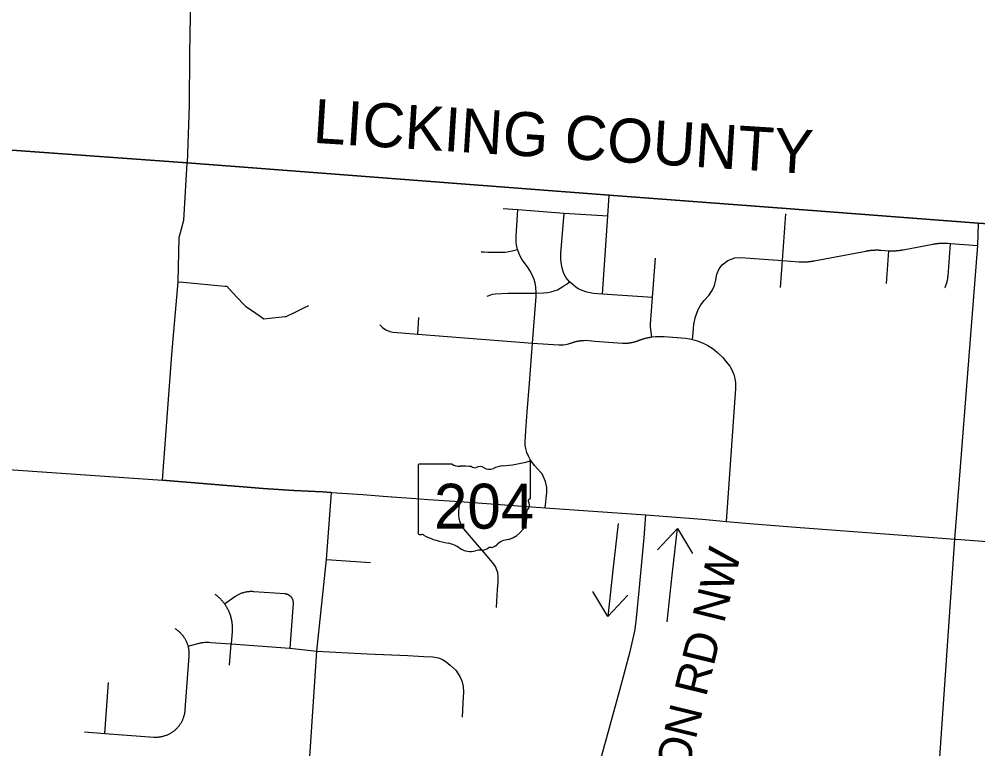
# Model space of a CAD drawing. Extents: x 1880545 to 1948545, y 79309 to 723051.
# Drawn here: x 1902373 to 1910544, y 700619 to 706837 of the extents above; entities that cross this region are included whole.
import ezdxf

# ---------------------------------------------------------------- set-up
doc = ezdxf.new("R2010")
doc.units = 0
for name, color, linetype in [('GM_X_County', 7, 'Continuous'), ('GM_X_County_Road', 7, 'Continuous'), ('GM_X_County_Text', 7, 'Continuous'), ('GM_X_State_Route', 7, 'Continuous'), ('GM_X_State_Shield', 7, 'Continuous'), ('GM_X_Township', 7, 'Continuous'), ('GM_X_Township_Road', 7, 'Continuous'), ('SH_Text', 7, 'Continuous')]:
    doc.layers.add(name, color=color, linetype=linetype)

msp = doc.modelspace()

# ---------------------------------------------------------------- linework, layer by layer
at = {"layer": 'GM_X_County'}
msp.add_lwpolyline([(1889271.5, 706620), (1891302.3, 706476.1), (1891973.7, 706452.7), (1893110.2, 706354.4), (1893306.8, 706337.4), (1894183.2, 706296.7), (1895332.2, 706215.1), (1898402.8, 705973), (1899946.7, 705888.4), (1900524.2, 705848.3), (1900987.7, 705813.2), (1901285.2, 705793.5), (1903803.3, 705612.3), (1907401, 705337.3), (1908909.6, 705222.3), (1910547.6, 705097.3), (1912287.5, 704989.5), (1913212.7, 704930.7), (1917682.9, 704647.7), (1918575.4, 704595.6), (1920101.7, 704497.5), (1921284.7, 704420.1), (1922414.3, 704343.6)], dxfattribs=at)
at = {"layer": 'GM_X_County_Road'}
for points in [[(1903834.8, 707192.1), (1903824.1, 706540.4), (1903822.2, 706103.6), (1903804.5, 705609.5)], [(1903743.6, 694852), (1904498.8, 695752), (1905984.5, 697482.2), (1906225.1, 697771.5), (1906330.5, 697904), (1906381.8, 698004.1), (1906482, 698229.9), (1906716.2, 698785.5), (1907022.1, 699505.3), (1907083, 699653.2), (1907147.2, 699860.4), (1907496.4, 701130), (1907579.5, 701447.1), (1907619.5, 701622.3), (1907630.8, 701703.2), (1907657.6, 701964), (1907699.4, 702415.6), (1907714.4, 702613)]]:
    msp.add_lwpolyline(points, dxfattribs=at)
at = {"layer": 'GM_X_State_Route'}
for p, q in [((1905552.5, 702766.9), (1905752.6, 702752.3)), ((1910015.3, 702431.2), (1910347, 702406.2)), ((1910347, 702406.2), (1910357.4, 702405.4)), ((1910357.4, 702405.4), (1910398.8, 702402.3))]:
    msp.add_line(p, q, dxfattribs=at)
for points in [[(1900688.5, 703112.5), (1900757.4, 703108), (1900954.3, 703093.6), (1901198.8, 703075.6), (1901679.7, 703043.6), (1902114.7, 703011.5), (1903595.5, 702908.8)], [(1903595.5, 702908.8), (1904451.7, 702836.1), (1904713.5, 702819.8), (1904959.1, 702807.4), (1905034.1, 702803)], [(1905034.1, 702803), (1905302.4, 702787.1), (1905547.2, 702767.3), (1905552.5, 702766.9)], [(1905752.6, 702752.3), (1905857.9, 702744.7), (1906127.5, 702727.2), (1906856.4, 702672.5), (1907714.4, 702613)], [(1907714.4, 702613), (1908192.9, 702574.4), (1908345.9, 702560.9)], [(1908345.9, 702560.9), (1908398.6, 702556.2), (1908634.1, 702537.2), (1908993.6, 702508), (1910015.3, 702431.2)], [(1910398.8, 702402.3), (1910957.8, 702359.4), (1912249.8, 702259.9), (1913033.6, 702197.6), (1913512.8, 702171.7), (1914434, 702136.7), (1915384.7, 702102.2), (1916119.3, 702053.7), (1916581.5, 702016.7), (1916959.5, 701996.7), (1917882.4, 701932.2)]]:
    msp.add_lwpolyline(points, dxfattribs=at)
at = {"layer": 'GM_X_State_Shield'}
for p, q in [((1906730.4, 702755.3), (1906730.4, 703059.3)), ((1905773.3, 703034.9), (1905773.3, 702453.8)), ((1906063, 703044.9), (1905782.7, 703044.9)), ((1906730.3, 702755.4), (1906730.4, 702755.3))]:
    msp.add_line(p, q, dxfattribs=at)
for centre, major_axis, start_param, end_param in [((1906389.5, 703837.2), (1015, 0), 4.814394, 5.042369), ((1906719.8, 703060.6), (10.7, 0), 6.141152, 7.989035), ((1905784.2, 703036.2), (11.1, 0), 1.712693, 3.28349), ((1906129.8, 703112.4), (107.5, 0), 4.042523, 4.731795), ((1906165.4, 702718.7), (386.1, 0), 1.404758, 1.657858), ((1906253.1, 703039.2), (31, 0), 3.836095, 5.185415), ((1906298.6, 702972), (64.5, 0), 0.950623, 2.079405), ((1906381.9, 703064.2), (77.6, 0), 4.081561, 5.145723), ((1906518.9, 702867.4), (204.2, 0), 1.699011, 2.107814), ((1906727.9, 702733), (16.5, 0), 1.883978, 3.671073), ((1906719, 702754.2), (11.4, 0), 5.05454, 6.418171), ((1906768.6, 702628.1), (72, 0), 2.387724, 3.262537), ((1906623, 702694.6), (99, 0), 5.934695, 6.695948), ((1906446.3, 702589.4), (253.9, 0), 5.101752, 6.440018), ((1905784.3, 702452.5), (11.2, 0), 3.00124, 4.508301), ((1905786, 702512), (85.4, 0), 4.665946, 4.897461), ((1905803.5, 702420.3), (30.8, 0), 0.519207, 1.627899), ((1906192.1, 702942.4), (733, 0), 4.195997, 4.488961), ((1905973.6, 702192.7), (229.3, 0), 0.823519, 1.323587), ((1906221.6, 702417.4), (145.5, 0), 4.026481, 4.996735), ((1906316.4, 702373.9), (77.5, 0), 4.691044, 5.507374), ((1906386.5, 702317.6), (21.8, 0), 1.147584, 2.315152), ((1906377.2, 702397.5), (82, 0), 4.937069, 5.64225), ((1906553.4, 702290.6), (139, 0), 1.647645, 2.488434), ((1906305.7, 702216.5), (119.6, 0), 1.495662, 1.94098)]:
    msp.add_ellipse(centre, major_axis=major_axis, ratio=0.8, start_param=start_param, end_param=end_param, dxfattribs=at)
at = {"layer": 'GM_X_Township'}
for points in [[(1922414.3, 704343.6), (1921284.7, 704420.1), (1920101.7, 704497.5), (1918575.4, 704595.6), (1917682.9, 704647.7), (1913212.7, 704930.7), (1912287.5, 704989.5), (1910547.6, 705097.3), (1908909.6, 705222.3), (1907401, 705337.3), (1903803.3, 705612.3), (1901285.2, 705793.5), (1900987.7, 705813.2), (1900524.2, 705848.3), (1899946.7, 705888.4), (1898402.8, 705973), (1895332.2, 706215.1), (1894183.2, 706296.7), (1893306.8, 706337.4), (1893110.2, 706354.4), (1891973.7, 706452.7), (1891302.3, 706476.1), (1889271.5, 706620), (1889456, 709272.2)], [(1901285.2, 705793.5), (1903803.3, 705612.3), (1907401, 705337.3), (1908909.6, 705222.3), (1910547.6, 705097.3), (1912287.5, 704989.5), (1913212.7, 704930.7), (1913032.4, 702200.4), (1912536.5, 694688.9), (1912502.9, 694180), (1912347.1, 691452.4), (1912324.5, 691136.3)]]:
    msp.add_lwpolyline(points, dxfattribs=at)
at = {"layer": 'GM_X_Township_Road'}
for p, q in [((1909765.6, 704584.5), (1909786.3, 704863.7)), ((1910310.1, 704925.6), (1910543.7, 704908.7)), ((1905771.2, 704152.8), (1905779.1, 704293.3)), ((1904991.6, 702232.3), (1905368.2, 702205.6)), ((1904166.7, 701332.6), (1904180, 701512.1)), ((1903103.2, 700750), (1903135.1, 701183.8))]:
    msp.add_line(p, q, dxfattribs=at)
for points in [[(1903595.5, 702908.8), (1903673.8, 703980.5), (1903727.5, 704598.7), (1903736.8, 704975.6), (1903776.4, 705124), (1903804.5, 705609.5)], [(1907344.1, 704494.7), (1907390, 705159.9), (1907402.2, 705334.5)], [(1906499.1, 705223.2), (1906623.5, 705213.6), (1907016.6, 705183.2), (1907390, 705159.9)], [(1906748.6, 704076.5), (1906778.6, 704473.7), (1906778.3, 704503), (1906775.9, 704555.1), (1906770.3, 704586.9), (1906761.8, 704618.3), (1906743.6, 704663.3), (1906726.4, 704695), (1906705.6, 704725.4), (1906676.6, 704764), (1906657.6, 704792.4), (1906640.3, 704822.4), (1906630.2, 704846.3), (1906619.8, 704873.7), (1906615.9, 704899), (1906613, 704913.4), (1906610.2, 704931.1), (1906609.7, 704953.6), (1906610.2, 704983.6), (1906613, 705031), (1906623.5, 705213.6)], [(1907770.7, 704465.4), (1907344.1, 704494.7), (1907269.3, 704499.9), (1907238.6, 704503.6), (1907210.3, 704509.9), (1907170.7, 704523.9), (1907138.6, 704539.5), (1907116.8, 704554.3), (1907094, 704572.1), (1907063.3, 704597.4), (1907035.9, 704632.4), (1907016.4, 704668.8), (1907000.5, 704714.8), (1906991.2, 704762.4), (1906989.2, 704794.8), (1906990.9, 704843.4), (1906995.9, 704908.3), (1907016.6, 705183.2)], [(1908861, 704551.2), (1908878.1, 704780.6), (1908907.6, 705177)], [(1910347, 702406.2), (1910543.7, 704908.7), (1910548.7, 705094.5)], [(1906311.3, 704854), (1906335.6, 704853.3), (1906366.9, 704851.7), (1906408.8, 704851.5), (1906454.8, 704850.6), (1906491.7, 704850.7), (1906515.2, 704851.9), (1906532.3, 704854.4), (1906574.7, 704862.6), (1906619.8, 704873.7)], [(1908878.1, 704780.6), (1909020.2, 704770), (1909024.2, 704769.7), (1909028.2, 704769.5), (1909032.1, 704769.3), (1909036.1, 704769.1), (1909040.1, 704768.9), (1909044.1, 704768.8), (1909048.2, 704768.7), (1909052.2, 704768.7), (1909056.2, 704768.6), (1909060.1, 704768.6), (1909064.1, 704768.7), (1909068.1, 704768.7), (1909072.1, 704768.9), (1909076.1, 704769), (1909080.1, 704769.2), (1909084.1, 704769.4), (1909088.1, 704769.6), (1909092.1, 704769.9), (1909096.1, 704770.1), (1909100.1, 704770.5), (1909104.1, 704770.8), (1909108.1, 704771.2), (1909112, 704771.7), (1909116, 704772.1), (1909120, 704772.6), (1909123.9, 704773.1), (1909127.9, 704773.7), (1909131.9, 704774.2), (1909135.8, 704774.8), (1909139.8, 704775.5), (1909143.7, 704776.2), (1909147.6, 704776.9), (1909589.9, 704861.1), (1909593.9, 704861.8), (1909597.8, 704862.5), (1909601.8, 704863.2), (1909605.7, 704863.8), (1909609.7, 704864.4), (1909613.6, 704865), (1909617.6, 704865.5), (1909621.5, 704866), (1909625.5, 704866.5), (1909629.5, 704867), (1909633.5, 704867.4), (1909637.5, 704867.8), (1909641.4, 704868.1), (1909645.4, 704868.4), (1909649.4, 704868.7), (1909653.4, 704869), (1909657.4, 704869.2), (1909661.4, 704869.4), (1909665.4, 704869.6), (1909669.4, 704869.7), (1909673.4, 704869.8), (1909677.4, 704869.8), (1909681.4, 704869.9), (1909685.4, 704869.9), (1909689.4, 704869.8), (1909693.4, 704869.8), (1909697.4, 704869.7), (1909701.4, 704869.6), (1909705.4, 704869.4), (1909709.4, 704869.2), (1909713.4, 704869), (1909717.4, 704868.7), (1909786.3, 704863.7)], [(1909786.3, 704863.7), (1909790.3, 704863.5), (1909794.3, 704863.3), (1909798.3, 704863.2), (1909802.3, 704863), (1909806.3, 704863), (1909810.3, 704862.9), (1909814.3, 704862.9), (1909818.3, 704862.9), (1909822.3, 704863), (1909826.3, 704863), (1909830.3, 704863.2), (1909834.3, 704863.3), (1909838.3, 704863.5), (1909842.3, 704863.7), (1909846.3, 704863.9), (1909850.3, 704864.2), (1909854.3, 704864.5), (1909858.3, 704864.8), (1909862.2, 704865.2), (1909866.2, 704865.6), (1909870.2, 704866), (1909874.2, 704866.5), (1909878.1, 704867), (1909882.1, 704867.5), (1909886.1, 704868), (1909890, 704868.6), (1909894, 704869.3), (1909897.9, 704869.9), (1909901.9, 704870.6), (1909907.7, 704871.7), (1910159.9, 704919.6), (1910163.9, 704920.3), (1910167.8, 704921), (1910171.7, 704921.7), (1910175.7, 704922.3), (1910179.6, 704922.9), (1910183.6, 704923.5), (1910187.6, 704924), (1910191.5, 704924.5), (1910195.5, 704925), (1910199.5, 704925.5), (1910203.5, 704925.9), (1910207.4, 704926.2), (1910211.4, 704926.6), (1910215.4, 704926.9), (1910219.4, 704927.2), (1910223.4, 704927.5), (1910227.4, 704927.7), (1910231.4, 704927.9), (1910235.4, 704928.1), (1910239.4, 704928.2), (1910243.4, 704928.2), (1910247.4, 704928.3), (1910251.4, 704928.3), (1910255.4, 704928.3), (1910259.4, 704928.3), (1910263.4, 704928.2), (1910267.4, 704928.2), (1910271.4, 704928), (1910275.4, 704927.9), (1910279.4, 704927.7), (1910283.4, 704927.5), (1910289.2, 704927.1), (1910310.1, 704925.6)], [(1910262.8, 704547.4), (1910264.3, 704550.6), (1910266, 704554.2), (1910267.6, 704557.8), (1910269.2, 704561.5), (1910270.7, 704565.2), (1910272.2, 704568.9), (1910273.6, 704572.7), (1910275, 704576.4), (1910276.3, 704580.2), (1910277.5, 704584), (1910278.8, 704587.8), (1910279.9, 704591.7), (1910281, 704595.5), (1910282, 704599.4), (1910283, 704603.2), (1910283.9, 704607.2), (1910284.8, 704611.1), (1910285.6, 704615), (1910286.3, 704618.9), (1910287, 704622.8), (1910287.6, 704626.8), (1910288.2, 704630.7), (1910288.7, 704634.7), (1910289.2, 704638.7), (1910289.6, 704642.7), (1910289.9, 704646.7), (1910310.1, 704925.6)], [(1907764.8, 704128.3), (1907753.7, 704212.2), (1907752.9, 704236.2), (1907770.7, 704465.4), (1907797.7, 704799.3)], [(1908111.9, 704106.7), (1908116.4, 704162.2), (1908119.8, 704204.8), (1908123.2, 704238.9), (1908136.1, 704299.3), (1908161.4, 704363.5), (1908183.3, 704402.1), (1908210.4, 704439.3), (1908250.6, 704482.9), (1908280.5, 704525.3), (1908299.6, 704568.2), (1908310.3, 704614.4), (1908319, 704663), (1908339.2, 704708.7), (1908365.4, 704743.2), (1908413.9, 704780.7), (1908471.9, 704801.9), (1908522.7, 704805.3), (1908600, 704799.5), (1908878.1, 704780.6)], [(1903727.5, 704598.7), (1903771.7, 704594.7), (1904125.4, 704562.3), (1904141.6, 704560.9), (1904191.3, 704508), (1904282.7, 704411.1), (1904305, 704387.4), (1904351.7, 704356), (1904425.4, 704306.5), (1904458.7, 704284.2), (1904507.2, 704289), (1904639.7, 704302.3), (1904649.3, 704303.3), (1904720.4, 704338), (1904800.2, 704377), (1904840.3, 704396.6)], [(1906778.3, 704503), (1906841.5, 704505.3), (1906874.6, 704507.8), (1906907.2, 704513.7), (1906940.1, 704523.3), (1906961.5, 704531.5), (1906984.3, 704544), (1907006, 704557.5), (1907024.1, 704569.8), (1907042.3, 704582.6), (1907063.3, 704597.4)], [(1906361.9, 704477.5), (1906392.9, 704487.7), (1906408.5, 704492.4), (1906432.6, 704496.6), (1906538.2, 704502.9), (1906778.3, 704503)], [(1905445.7, 704232.8), (1905468.1, 704209.3), (1905497.3, 704190.5), (1905532.9, 704175.8), (1905559, 704169), (1905771.2, 704152.8), (1906748.6, 704076.5), (1906973.8, 704060.4), (1906978.6, 704060.2), (1907011.2, 704061.3), (1907043.7, 704065.8), (1907074.6, 704076.2), (1907077.8, 704077.3), (1907081.6, 704078.6), (1907085.4, 704079.9), (1907090.7, 704081.7), (1907094.5, 704083), (1907098.3, 704084.3), (1907102.1, 704085.5), (1907106, 704086.6), (1907109.8, 704087.7), (1907113.7, 704088.7), (1907117.5, 704089.8), (1907121.4, 704090.7), (1907125.3, 704091.6), (1907129.3, 704092.4), (1907133.2, 704093.2), (1907137.1, 704093.9), (1907141, 704094.6), (1907145, 704095.2), (1907148.9, 704095.8), (1907152.9, 704096.4), (1907156.9, 704096.8), (1907160.9, 704097.2), (1907164.9, 704097.6), (1907168.8, 704097.9), (1907172.8, 704098.2), (1907176.8, 704098.4), (1907180.8, 704098.5), (1907184.8, 704098.6), (1907188.8, 704098.7), (1907198.6, 704100.8), (1907278.1, 704093.3), (1907476.5, 704079.7), (1907517.8, 704076.8), (1907522.5, 704076.6), (1907526.5, 704076.4), (1907530.5, 704076.2), (1907534.5, 704076.2), (1907538.5, 704076.2), (1907542.5, 704076.2), (1907546.5, 704076.2), (1907550.5, 704076.4), (1907554.5, 704076.6), (1907558.5, 704076.8), (1907562.5, 704077.1), (1907566.5, 704077.5), (1907570.4, 704077.9), (1907574.4, 704078.3), (1907578.4, 704078.8), (1907582.3, 704079.4), (1907586.3, 704080), (1907590.2, 704080.6), (1907594.2, 704081.4), (1907598.1, 704082.1), (1907602, 704082.9), (1907605.9, 704083.8), (1907609.8, 704084.7), (1907613.7, 704085.7), (1907617.5, 704086.7), (1907621.4, 704087.8), (1907625.2, 704089), (1907629.1, 704090.2), (1907632.9, 704091.4), (1907636.6, 704092.7), (1907640.4, 704094), (1907644.2, 704095.4), (1907647.9, 704096.8), (1907652.9, 704098.8), (1907656.6, 704100.2), (1907660.4, 704101.7), (1907664.1, 704103.1), (1907667.9, 704104.4), (1907671.7, 704105.7), (1907675.4, 704107), (1907679.3, 704108.3), (1907683.1, 704109.5), (1907686.9, 704110.7), (1907690.7, 704111.9), (1907694.5, 704113), (1907698.4, 704114.1), (1907702.2, 704115.2), (1907706.1, 704116.3), (1907709.9, 704117.3), (1907713.8, 704118.3), (1907717.7, 704119.2), (1907721.6, 704120.1), (1907725.5, 704121.1), (1907729.4, 704121.9), (1907733.3, 704122.7), (1907737.2, 704123.6), (1907741.2, 704124.3), (1907745.1, 704125.1), (1907749, 704125.8), (1907753, 704126.4), (1907756.9, 704127.1), (1907760.9, 704127.7), (1907764.8, 704128.3), (1907795.7, 704131.7), (1907834.6, 704133.3), (1907869.6, 704132.1), (1907943.6, 704126.2), (1908052.8, 704117), (1908089.4, 704111.5), (1908111.9, 704106.7), (1908152.5, 704095.2), (1908201.8, 704076.1), (1908242.8, 704055.2), (1908286.6, 704027.3), (1908325.8, 703996.3), (1908369.1, 703953.3), (1908400.2, 703917.1), (1908430, 703878.4), (1908447.4, 703848.1), (1908464.1, 703807.5), (1908472.9, 703774.6), (1908478.1, 703738), (1908478, 703688.9), (1908398.6, 702556.2)], [(1906819.9, 702972.4), (1906792.9, 703003.1), (1906768.4, 703030.9), (1906747.1, 703056.6), (1906728.4, 703084.3), (1906712.9, 703113.9), (1906700.4, 703144.8), (1906690.8, 703176.8), (1906685.9, 703206.4), (1906685.2, 703234.3), (1906687, 703277.2), (1906690.4, 703332.4), (1906702.1, 703489.9), (1906722.6, 703735.8), (1906748.6, 704076.5)], [(1905034.1, 702803), (1904959.1, 702807.4), (1904713.5, 702819.8), (1904451.7, 702836.1), (1903595.5, 702908.8)], [(1906856.4, 702672.5), (1906870.3, 702804.2), (1906871.1, 702846.3), (1906860, 702898), (1906830, 702960.9), (1906819.9, 702972.4)], [(1904498.8, 695752), (1904699.2, 698459.7), (1904747.1, 699083.9), (1904795.5, 699734.1), (1904909.4, 701450.1), (1904991.6, 702232.3), (1905034.1, 702803)], [(1906440, 701823), (1906450.2, 701975.2), (1906454.8, 702038.4), (1906455.9, 702085.1), (1906451.3, 702118.3), (1906441.3, 702150.3), (1906434.3, 702165.6), (1906425.9, 702180.2), (1906406.5, 702207.2), (1906332.7, 702295.1), (1906279, 702357), (1906163, 702494.7), (1906144, 702520.6), (1906130.1, 702548.8), (1906122.8, 702579.6), (1906120.6, 702611.7), (1906121.2, 702644.2), (1906127.5, 702727.2)], [(1909204, 694397.9), (1909237.3, 694606.7), (1909274.6, 694755.9), (1909351.4, 694905.3), (1909471.8, 695025), (1909703.6, 695238.2), (1909815.5, 695374.1), (1909874.1, 695504.6), (1909911.4, 695648.5), (1909954.1, 696077.5), (1910139.3, 699387.4), (1910347, 702406.2)], [(1904041.3, 701937.9), (1904047.2, 701933.5), (1904053, 701928.9), (1904058.6, 701924.3), (1904064.2, 701919.5), (1904069.7, 701914.6), (1904075.1, 701909.6), (1904080.4, 701904.4), (1904085.5, 701899.2), (1904090.6, 701893.9), (1904095.6, 701888.5), (1904100.4, 701883), (1904105.2, 701877.3), (1904109.8, 701871.6), (1904114.3, 701865.8), (1904118.7, 701859.9), (1904122.9, 701853.9), (1904127.2, 701847.7), (1904131.3, 701841.4), (1904135.3, 701835), (1904139.2, 701828.5), (1904142.9, 701821.9), (1904146.5, 701815.2), (1904150, 701808.5), (1904153.3, 701801.7), (1904156.5, 701794.9), (1904159.5, 701788), (1904162.4, 701781), (1904165.2, 701773.9), (1904167.8, 701766.8), (1904170.2, 701759.7), (1904172.5, 701752.5), (1904174.7, 701745.2), (1904176.7, 701737.9), (1904178.5, 701730.6), (1904180.2, 701723.3), (1904181.8, 701715.9), (1904183.2, 701708.4), (1904184.4, 701701), (1904185.5, 701693.5), (1904186.4, 701686), (1904187.2, 701678.5), (1904187.8, 701670.9), (1904188.3, 701663.4), (1904188.6, 701655.8), (1904188.7, 701648.3), (1904188.7, 701640.7), (1904188.6, 701633.2), (1904188.2, 701625.6), (1904187.8, 701618.1), (1904180, 701512.1)], [(1904122.9, 701853.9), (1904211.8, 701916), (1904216.8, 701919.4), (1904221.9, 701922.7), (1904227.1, 701925.9), (1904232.4, 701929), (1904237.8, 701931.9), (1904243.2, 701934.7), (1904248.7, 701937.3), (1904254.2, 701939.9), (1904259.8, 701942.3), (1904265.5, 701944.5), (1904271.2, 701946.6), (1904277, 701948.6), (1904282.8, 701950.4), (1904288.7, 701952.1), (1904294.6, 701953.7), (1904300.5, 701955.1), (1904306.5, 701956.3), (1904312.5, 701957.4), (1904318.5, 701958.4), (1904324.6, 701959.2), (1904330.6, 701959.9), (1904336.7, 701960.4), (1904342.8, 701960.8), (1904348.9, 701961), (1904355, 701961.1), (1904361.1, 701961), (1904367.2, 701960.7), (1904373.3, 701960.4), (1904637.4, 701940.9), (1904640.8, 701940.6), (1904644.1, 701940.1), (1904647.4, 701939.5), (1904650.7, 701938.7), (1904653.9, 701937.8), (1904657.1, 701936.8), (1904660.2, 701935.6), (1904663.3, 701934.2), (1904666.4, 701932.7), (1904669.3, 701931.1), (1904672.2, 701929.4), (1904675, 701927.5), (1904677.7, 701925.5), (1904680.3, 701923.4), (1904682.8, 701921.2), (1904685.3, 701918.8), (1904687.6, 701916.4), (1904689.8, 701913.8), (1904691.8, 701911.2), (1904693.8, 701908.5), (1904695.6, 701905.6), (1904697.4, 701902.7), (1904698.9, 701899.8), (1904700.4, 701896.7), (1904701.7, 701893.6), (1904702.8, 701890.5), (1904703.9, 701887.2), (1904704.7, 701884), (1904705.5, 701880.7), (1904706, 701877.4), (1904706.5, 701874.1), (1904706.8, 701870.7), (1904706.9, 701867.3), (1904706.9, 701864), (1904706.7, 701860.6), (1904678.3, 701475.4)], [(1902928.6, 700762.8), (1903103.2, 700750), (1903519.9, 700719.3), (1903526.2, 700718.9), (1903532.4, 700718.6), (1903538.6, 700718.6), (1903544.8, 700718.7), (1903551.1, 700718.9), (1903557.3, 700719.3), (1903563.5, 700719.8), (1903569.7, 700720.6), (1903575.9, 700721.4), (1903582, 700722.4), (1903588.1, 700723.6), (1903594.2, 700724.9), (1903600.3, 700726.4), (1903606.3, 700728), (1903612.3, 700729.8), (1903618.2, 700731.7), (1903624.1, 700733.8), (1903629.9, 700736), (1903635.7, 700738.3), (1903641.4, 700740.8), (1903647.1, 700743.5), (1903652.6, 700746.3), (1903658.1, 700749.2), (1903663.6, 700752.2), (1903668.9, 700755.4), (1903674.2, 700758.7), (1903679.4, 700762.2), (1903684.5, 700765.8), (1903689.5, 700769.5), (1903694.4, 700773.3), (1903699.2, 700777.3), (1903704, 700781.3), (1903708.6, 700785.5), (1903713.1, 700789.8), (1903717.5, 700794.2), (1903721.8, 700798.8), (1903726, 700803.4), (1903730, 700808.1), (1903734, 700813), (1903737.8, 700817.9), (1903741.5, 700822.9), (1903745, 700828), (1903748.5, 700833.2), (1903751.8, 700838.5), (1903755, 700843.8), (1903758, 700849.3), (1903760.9, 700854.8), (1903763.7, 700860.4), (1903766.3, 700866), (1903768.8, 700871.8), (1903771.1, 700877.5), (1903773.3, 700883.4), (1903775.4, 700889.3), (1903777.3, 700895.2), (1903779, 700901.2), (1903780.6, 700907.2), (1903782.1, 700913.3), (1903783.4, 700919.3), (1903784.6, 700925.5), (1903785.5, 700931.6), (1903786.4, 700937.8), (1903787.1, 700944), (1903787.6, 700950.2), (1903821.4, 701409.4), (1903821.8, 701415.4), (1903822, 701421.5), (1903822.1, 701427.5), (1903822.1, 701433.5), (1903821.8, 701439.6), (1903821.5, 701445.6), (1903821, 701451.6), (1903820.3, 701457.6), (1903819.6, 701463.6), (1903818.6, 701469.5), (1903817.5, 701475.4), (1903816.3, 701481.4), (1903815, 701487.2), (1903813.4, 701493.1), (1903811.7, 701499.1), (1903809.8, 701505.2), (1903807.8, 701511.1), (1903805.6, 701517.1), (1903803.3, 701522.9), (1903800.8, 701528.7), (1903798.2, 701534.5), (1903795.5, 701540.1), (1903792.5, 701545.7), (1903789.5, 701551.3), (1903786.3, 701556.7), (1903783, 701562.1), (1903779.5, 701567.4), (1903775.9, 701572.6), (1903772.2, 701577.6), (1903768.4, 701582.7), (1903764.4, 701587.6), (1903760.3, 701592.4), (1903756.1, 701597.1), (1903751.8, 701601.6), (1903747.3, 701606.1), (1903742.8, 701610.5), (1903738.1, 701614.7), (1903733.3, 701618.9), (1903728.5, 701622.9), (1903723.5, 701626.8), (1903718.4, 701630.5), (1903713.3, 701634.1), (1903708, 701637.6), (1903702.7, 701641)], [(1903813.4, 701493.1), (1903906.2, 701518.2), (1903912, 701519.7), (1903917.9, 701521), (1903923.8, 701522.2), (1903929.7, 701523.3), (1903935.7, 701524.3), (1903941.6, 701525), (1903947.6, 701525.7), (1903953.7, 701526.2), (1903959.7, 701526.5), (1903965.7, 701526.8), (1903971.7, 701526.8), (1903977.8, 701526.7), (1903983.8, 701526.5), (1903989.8, 701526.2), (1904005.4, 701525), (1904180, 701512.1), (1904678.3, 701475.4), (1904909.4, 701450.1)], [(1904909.4, 701450.1), (1905337.6, 701429.5), (1905684.4, 701412.9), (1905822.2, 701406.1), (1905898.6, 701401.9), (1905947.7, 701394.2), (1905982.3, 701380.6), (1906012.3, 701359.2), (1906046, 701332.3), (1906093.4, 701287.8), (1906129, 701235), (1906146.1, 701197.1), (1906157.9, 701150.1), (1906158.6, 701104.3), (1906155.6, 701009.8), (1906149.7, 700887.4)]]:
    msp.add_lwpolyline(points, dxfattribs=at)
at = {"layer": 'SH_Text'}
for p, q in [((1907477.2, 702540), (1907433.1, 702142.5)), ((1907983.6, 702497.1), (1907812.5, 702314.9)), ((1907939.5, 702099.5), (1907983.6, 702497.1)), ((1907983.6, 702497.1), (1908110.6, 702281.8)), ((1907433.1, 702142.5), (1907389.1, 701744.9)), ((1907895.4, 701702), (1907939.5, 702099.5)), ((1907389.1, 701744.9), (1907262, 701960.2)), ((1907389.1, 701744.9), (1907560.2, 701927.2))]:
    msp.add_line(p, q, dxfattribs=at)

# ---------------------------------------------------------------- texts
at = {"layer": 'GM_X_County_Text'}
msp.add_text('LICKING COUNTY', height=375, rotation=356.39956, dxfattribs=at).set_placement((1904871.3, 705783.9))
at = {"layer": 'GM_X_State_Shield'}
msp.add_text('204', height=382.85, dxfattribs=at).set_placement((1905908.4, 702494.8))
at = {"layer": 'SH_Text'}
msp.add_text('PICKERINGTON RD NW', height=279.999, rotation=76.25875, dxfattribs=at).set_placement((1907525.3, 698185))

doc.saveas('drawing.dxf')
